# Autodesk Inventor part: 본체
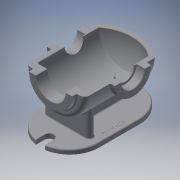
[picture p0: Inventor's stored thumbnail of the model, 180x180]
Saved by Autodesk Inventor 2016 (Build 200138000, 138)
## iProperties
Created: 2016-02
Part Number: 본체
Material: 알루미늄 6061
Document SubType Name: Modeling
Designer: mduedu
Density: 2.71 g/cm^3
Appearance: 기본값
Mass: 2164.68 g
Surface Area: 1516.74 cm^2
Volume: 798.775 cm^3
Author: mduedu
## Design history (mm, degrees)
sketch "스케치2"
  geometry: L1 (0, 90)-(0, -90); L2 (65, -65.993)-(65, 90); L3 (65, 90)-(0, 90); A1 r 100 centre (0, 10) between (0, -90) and (65, -65.993); 2 further points
  constraints: 6 end point, 2 point on circle, 1 centre point, 1 coincident, 1 horizontal, 1 midpoint, 1 parallel, 1 point on line, 1 vertical
  dimensions: "d3" = 180 distance of L1.start L1.end; "d5" = 130 diameter of L2 L1; "d6" = 100 radius of A1
revolve "회전1" sketch "스케치2" stored, may be unused: angle "d7" = 90 deg
sketch "스케치3"
  geometry: C1 r 47.5 at (0, 0); 1 further point
  constraints: 1 centre point, 1 coincident
  dimensions: "d8" = 95 diameter of C1
extrude "돌출2" join sketch "스케치3" distance "d10" = 10; taper "d11" = 0 deg
sketch "스케치5"
  geometry: L1 (47.5, 100)-(47.5, 90) reference; L2 (47.5, 90)-(65, 90) reference; L3 (65, 90)-(65, -65.993) reference; L4 (-65, -65.993)-(-65, 90) reference; L5 (-65, 90)-(-47.5, 90) reference; L6 (-47.5, 90)-(-47.5, 100) reference; L7 (-47.5, 100)-(47.5, 100) reference; L8 (55, 75)-(55, -61.239); L9 (0, 75)-(55, 75); L10 (0, 75)-(0, -80); A1 r 100 centre (0, 10) between (-65, -65.993) and (0, -90) reference; A2 r 100 centre (0, 10) between (0, -90) and (65, -65.993) reference; A3 r 90 centre (0, 10) between (0, -80) and (55, -61.239); 1 further point
  constraints: 6 end point, 2 point on circle, 1 centre point, 1 parallel, 1 perpendicular, 1 point on line, 1 vertical
  dimensions: "d13" = 10 distance between parallel lines of L3 L8; "d14" = 10 radial gap between concentric circles of A3 A1; "d15" = 15 distance between parallel lines of L9 L2
revolve "회전2" sketch "스케치5" stored, may be unused: angle "d16" = 90 deg
hole "구멍1" diameter "d19" = 65; stored, may be unused: countersink angle "d23" = 90 deg, drill point angle "d25" = 118 deg; dims "d17" = 10, "d18" = 10, "d20" = 6, "d21" = 4, "d22" = 2, "d24" = 8
node "작업 평면1"
sketch "스케치6"
  geometry: L1 (47.5, 100)-(-47.5, 100) reference; C1 r 40 at (0, -7); 1 further point
  constraints: 1 centre point, 1 vertical alignment
  dimensions: "d27" = 80 diameter of C1; "d29" = 107 distance from line of C1.centre L1
extrude "돌출3" join sketch "스케치6" stored distance "d30" = 10; taper "d31" = 0 deg
hole "구멍2" diameter "d34" = 42; stored, may be unused: countersink angle "d38" = 90 deg, drill point angle "d40" = 118 deg; dims "d32" = 10, "d33" = 10, "d35" = 6, "d36" = 52, "d37" = 18, "d39" = 8
sketch "스케치7" dims "d41" = 65
  geometry: C1 r 40 at (0, 0) reference; 3 further points
  constraints: 2 vertical alignment, 1 coincident, 2 other
hole "구멍3" sketch "스케치7" at (0, 32.5) diameter "d43" = 3.242; stored, may be unused: countersink angle "d47" = 90 deg, drill point angle "d49" = 118 deg; dims "d44" = 11, "d45" = 13, "d46" = 18, "d48" = 13
sketch "스케치8" dims "d53" = 80
  geometry: 3 further points
  constraints: 2 vertical alignment, 1 coincident, 2 other
hole "구멍4" sketch "스케치8" at (0, -40) diameter "d56" = 3.242; stored, may be unused: countersink angle "d60" = 90 deg, drill point angle "d62" = 118 deg; dims "d57" = 11, "d58" = 13, "d59" = 18, "d61" = 13
fillet "모깎기1" dims "d66" = 10
fillet "모깎기2" dims "d67" = 3
fillet "모깎기3" dims "d68" = 0.3
chamfer "모따기1" distance "d69" = 1; stored, may be unused: second distance "d70" = 2, angle "d71" = 45 deg
node "작업 평면5"
sketch "스케치10"
  geometry: L1 (-50, 66)-(50, 66); L2 (50, 66)-(50, 50); L3 (50, 50)-(-50, 50); L4 (-50, 50)-(-50, 66); 2 further points
  constraints: 8 end point, 2 horizontal, 2 vertical, 1 midpoint, 1 vertical alignment
  dimensions: "d177" = 50 distance from line of L3 point (0, 0); "d178" = 100 distance of L1.start L1.end; "d179" = 16 distance of L3.end L1.start
extrude "돌출5" join sketch "스케치10" stored distance "d84" = 10; taper "d85" = 0 deg
sketch "스케치21" dims "d180" = 220, "d182" = 130
  geometry: L1 (65, 58)-(-65, 58); L2 (-65, 58)-(-65, -32); L3 (-65, -32)-(65, -32); L4 (65, -32)-(65, 58); L5 (50, 50)-(50, 66) reference; 4 further points
  constraints: 8 end point, 3 horizontal alignment, 3 midpoint, 2 parallel, 1 horizontal, 1 perpendicular, 1 vertical alignment, 4 other
extrude "돌출13" join sketch "스케치21" distance "d183" = 10; taper "d184" = 0 deg
sketch "스케치11"
  geometry: L1 (-65, 80)-(-65, -61.239) reference; L2 (-100, -97)-(-100, -32) reference; L3 (-65, -42.793)-(-100, -63); L4 (-100, -97)-(-110, -97) reference; 1 further point
  constraints: 2 end point, 2 point on line
  dimensions: "d185" = 34 distance from line of L3.end L4; "d186" = 120 deg angle of L2 L3
feature "리브1" sketch "스케치11" dims "d88" = 1, "d89" = 16, "d90" = 0, "d91" = 0, "d92" = 1, "d93" = 1
fillet "모깎기12"
fillet "모깎기13"
fillet "모깎기16" dims "d167" = 3
fillet "모깎기18"
fillet "모깎기17" dims "d168" = 3
fillet "모깎기19" dims "d187" = 3
node "작업 평면6"
sketch "스케치19"
  geometry: L1 (75, -47)-(75, 33) reference; L2 (-75, -47)-(-75, 33) reference; L3 (75, -7)-(-75, -7); C1 r 22.5 at (0, -7); 1 further point
  constraints: 3 midpoint, 2 end point, 1 centre point
  dimensions: "d149" = 45 diameter of C1
extrude "돌출11" join sketch "스케치19" stored distance "d150" = 10; taper "d151" = 0 deg
hole "구멍6" diameter "d154" = 33.376; stored, may be unused: countersink angle "d158" = 90 deg, drill point angle "d160" = 118 deg; dims "d155" = 6, "d156" = 4, "d157" = 2, "d159" = 8, "d190" = 10, "d191" = 10
fillet "모깎기11" dims "d161" = 3
chamfer "모따기3" distance "d164" = 1; stored, may be unused: second distance "d165" = 2, angle "d166" = 45 deg
node "작업 평면9"
  node "작업 평면8"
sketch "스케치22" dims "d189" = 20
  geometry: L1 (-10, -123)-(10, -123); L2 (10, -123)-(10, -103); L3 (10, -103)-(-10, -103); L4 (-10, -103)-(-10, -123); A1 r 65 centre (0, -58) between (-65, -58) and (65, -58) reference; 2 further points
  constraints: 8 end point, 2 parallel, 1 horizontal, 1 horizontal alignment, 1 midpoint, 1 perpendicular, 1 tangent, 1 vertical alignment, 2 other
  dimensions: "d193" = 30 dimension on L1
extrude "돌출14" cut sketch "스케치22" stored distance "d194" = 10; taper "d195" = 0 deg
fillet "모깎기21" dims "d196" = 3
feature "분할1"
sketch "스케치23"
  geometry: L1 (-65, 32)-(-65, -58) reference; L2 (65, -58)-(65, 32) reference; L3 (-65, -13)-(65, -13); 2 further points
  constraints: 2 end point, 2 midpoint, 1 point on line, 1 other
  dimensions: "d197" = 12 distance from line of point (53, -13) L2
feature "엠보싱2" sketch "스케치23" dims "d8" = 95, "d198" = 0.5, "d199" = 0
node "솔리드2"
pattern_circular "원형 패턴1" dims angle "d51" = 360 deg
mirror "대칭1"
pattern_circular "원형 패턴2" dims angle "d64" = 360 deg
mirror "대칭3"
node "절단 모서리 투영1"
other parameters: "d26" = 75, "d136" = 175
